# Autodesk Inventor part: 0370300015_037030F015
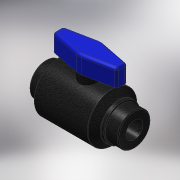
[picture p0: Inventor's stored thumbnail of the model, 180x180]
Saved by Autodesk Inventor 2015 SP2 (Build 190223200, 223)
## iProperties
Created: 2017-06
Part Number: 0370300015_037030F015
Material: PVC-Piping
Description: PLASSON BALL VALVE DN40 FEMALE 1.1/2" BSPT
Document SubType Name: Modeling
Designer: KIM
Mass: 1188.36 g
Surface Area: 731.841 cm^2
Volume: 848.83 cm^3
Density: 1.4 g/cm^3
Appearance: Black Cast
Author: KIM
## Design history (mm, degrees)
derived "03703.ipt"
feature "Solid1::03703.ipt"
tag "TaggingFeature1"
body "Solid1"
other parameters: "d0" = 144, "d4" = 24, "d5" = 44.845, "d6" = 44.845, "d7" = 24, "d8" = 65, "d9" = 19.2, "d10" = 71.5, "d11" = 15.0485, "d12" = 135 deg, "d14" = 2.24225, "d24" = 26.907, "d25" = 58.5, "d27" = 26.907, "d28" = 13.4535, "d29" = 28.5, "d30" = 0, "d32" = 59.1954, "d33" = 6.72675, "d34" = 2.24225, "Rc_" = 44.845, "A_1" = 45, "A_2" = 87, "H_" = 144, "l_" = 24, "B_" = 65, "E_" = 1, "d31" = 53.814
